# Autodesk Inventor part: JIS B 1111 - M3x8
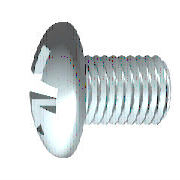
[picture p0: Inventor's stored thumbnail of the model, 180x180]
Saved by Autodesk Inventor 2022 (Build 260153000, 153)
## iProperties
IsCustomPart: 0
Created: 2021-02
Part Number: JIS B 1111 - M3x8
Material: 鋼、軟鋼
Description: トラス小ねじ
Document SubType Name: Modeling
Standard: JIS B 1111
Designer: shimizu
Standards Organization: JIS
Language: ja-JP
Size Designation: M3x8
Categories: <MemberInstance><Categories><Category DisplayName="締結器具" InternalName="e4da775c-781d-43d5-af7c-5136215cf5a6" Mnemonic="FSTN"><Category DisplayName="ボルト" Interna
Density: 7.85 g/cm^3
Appearance: 半つや出し
Author: shimizu
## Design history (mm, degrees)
pattern_circular "円形状配列1" dims angle "d36" = 360 deg
node "MSC_A1"
node "MSC_PF1"
node "MSC_PT1"
body "Solid1"
sketch "スケッチ2"
  geometry: L1 (-3.45, 0)-(-3.45, 0.343); L2 (-1.25, 0)-(-3.45, 0); L3 (-1.25, -1)-(-1.25, 0); L4 (-1.5, -1.5)-(-1.25, -1); L5 (-1.5, -8)-(-1.5, -1.5); L6 (0, -8)-(-1.5, -8); L7 (0, 1.9)-(0, -8); L8 (0, 8.529)-(0, -26.727); L9 (0, 1.9)-(0, -8); L10 (0, -33.778)-(0, 15.58) reference; L11 (0.724, 0)-(-4.341, 0) reference; A1 r 4.6 centre (0, -2.7) between (0, 1.9) and (-3.45, 0.343)
  constraints: 18 end point, 5 vertical, 2 horizontal, 2 point on circle, 1 centre point
  dimensions: "d1" = 1.25 horizontal distance of L2.start L7.start (= 0.5 x msp_ds); "d3" = 0.5 vertical distance of L4.start L3.start (= msp_x); "d5" = 1.9 vertical distance of L2.start L7.start (= ParK); "d7" = 0 horizontal distance of A1.centre L7.start; "d9" = 4.6 radius of A1 (= rf); "d11" = 3.45 horizontal distance of L1.end L7.start (= 0.5 x Dk); "d13" = 1.5 distance of L6.start L5.start (= 0.5 x NND); "d15" = 8 vertical distance of L1.start L6.start (= NLG); "d17" = 6.5 distance of L5.start L4.start (= b); "d19" = 0 horizontal distance of L8.start L7.start; "d30" = 0 distance between parallel lines of L11 L2; "d31" = 0 distance between parallel lines of L10 L7
revolve "回転1" stored, may be unused: angle "d20" = 360 deg
sketch "スケッチ3"
  geometry: L1 (-1.45, 1.9)-(0, 1.9); L2 (-0.242, 0.317)-(-1.45, 1.9); L3 (0, 0.317)-(-0.242, 0.317); L4 (0, 1.9)-(0, 0.317); L5 (-3.375, 0)-(3.375, 0); L6 (0, -0.38)-(0, 2.28) reference; L7 (4.725, 0)-(-4.725, 0) reference
  constraints: 10 end point, 2 horizontal, 1 vertical
  dimensions: "d22" = 1.45 distance of L1.start L1.end (= 0.5 x M); "d24" = 0.24167 distance of L3.start L2.start (= 0.0833333 x M); "d26" = 1.58333 distance of L1.end L3.start (= 0.833333 x ParK); "d32" = 1.9 distance between parallel lines of L7 L1 (= ParK); "d33" = 0 distance between parallel lines of L6 L4
extrude "押し出し1" cut sketch "スケッチ3" stored distance "d27" = 0.48333 (= 0.166667 x M); taper "d28" = 0 deg
fillet "フィレット1" dims "d29" = 0.1 (= r)
fillet "フィレット2" dims "d37" = 0.96667 (= msp_rr), "d38" = 0.001
fillet "フィレット3" dims "d39" = 0.96667 (= msp_rr), "d40" = 0.001
fillet "フィレット4" dims "d41" = 0.96667 (= msp_rr), "d42" = 0.001
fillet "フィレット5" dims "d43" = 0.001, "d44" = 0.96667 (= msp_rr)
feature "ねじ1" dims "d45" = 10, "d46" = 0
other parameters: "PTC" = 0.5 [user parameter; used in 2 equation terms], "NLG" = 8 [user parameter; used in 1 equation term], "Dk" = 6.9 [user parameter; used in 1 equation term], "ParK" = 1.9 [user parameter; used in 3 equation terms], "NND" = 3 [user parameter; used in 3 equation terms], "M" = 2.9 [user parameter; used in 4 equation terms], "r" = 0.1 [user parameter; used in 1 equation term], "rf" = 4.6 [user parameter; used in 1 equation term], "msp_ds" = 2.5 (= NND - PTC) [user parameter; used in 1 equation term], "msp_x" = 0.5 (= PTC) [user parameter; used in 1 equation term], "msp_rr" = 0.96667 (= 0.333333 x M) [user parameter; used in 4 equation terms], "b" = 6.5 [user parameter; used in 1 equation term], "d0" = 3.375 (derived), "d2" = 1.25 (derived), "d4" = 4.8 (derived), "d6" = 0 (derived), "d8" = 11.7 (derived), "d10" = 8.9 (derived), "d12" = 4 (derived), "d16" = 15 (derived), "d18" = 0 (derived), "d21" = 3.9 (derived), "d23" = 0.65 (derived), "d25" = 4 (derived), "d49" = 0, "d50" = 0, "d51" = 0, "d52" = 0, "d53" = 0, "THREADDIA" = 3 (= NND) [user parameter], "TEMPLATE" = 12.345 [user parameter]
